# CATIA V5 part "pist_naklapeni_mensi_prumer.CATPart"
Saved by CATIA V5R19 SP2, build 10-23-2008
Part number: Part1.2
Bounding box of the stored display mesh (mm): x -35 to 35, y -55 to 55, z 0 to 674.812
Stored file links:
  C:\Users\Martin\Desktop\9.semestr\Projekt-diplomka\3D model\pist_naklapeni_mensi_prumer.CATPart
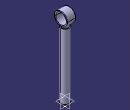
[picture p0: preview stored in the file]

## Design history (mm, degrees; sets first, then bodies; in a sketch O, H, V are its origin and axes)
Body1 (main body)
  Sketch1 on xy-plane, origin (0, 0, 0), H (1, 0, 0), V (0, 1, 0)
    circle A1 centre (0, 0) radius 35
    radius A1 = 35
  Pad1: profile Sketch1, direction (0, 0, 1), length 550
  Sketch2 on yz-plane, origin (0, 0, 0), H (0, 1, 0), V (0, 0, 1)
    circle A1 centre (0, 620) radius 45
    point P1 (0, 620)
    circle A2 centre (0, 620) radius 55
    reference projected line E1 (-35, 550) -> (35, 550) from edge [face of Pad1 from Sketch1.A1 | end face of Pad1]
    distance P1 E1 = 70
    radius A2 = 55
    radius A1 = 45
    coincidence: P1 V
    concentricity: A2 A1
  Pad2: profile Sketch2, direction (1, 0, 0), length 34, mirrored extent
  Sketch3 on end face of Pad1, origin (0, 0, 550), H (1, 0, 0), V (0, 1, 0)
    circle A1 centre (0, 0) radius 27.5
    radius A1 = 27.5
  Pad3: profile Sketch3, direction (0, 0, 1), up to the existing solid (limit type 2)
